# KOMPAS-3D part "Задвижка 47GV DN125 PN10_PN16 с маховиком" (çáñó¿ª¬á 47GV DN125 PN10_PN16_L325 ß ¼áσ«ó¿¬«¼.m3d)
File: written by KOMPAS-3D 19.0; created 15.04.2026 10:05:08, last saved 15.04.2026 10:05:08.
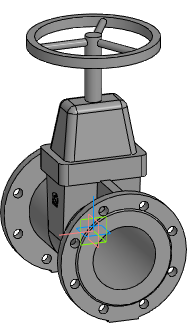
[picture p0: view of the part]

Document properties: Автор: Евгений; Полное имя файла: Z:\3.Личные\kachalov\3d для проектировщиков\2.1 Тип 47GV, 47GV.Z\Задвижка 47GV_DN40-DN600\stp_Задвижка 47GV\Задвижка 47GV DN125 PN10_PN16_L325 с маховиком.m3d

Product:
- Part/product: Задвижка 47GV DN125 PN10_PN16 с маховиком

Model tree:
1. Операция без истории:1  (labels: Задвижка 47GV DN125 PN10_PN16 с маховиком)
